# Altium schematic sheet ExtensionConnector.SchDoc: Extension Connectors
size A4; DocumentNumber: MB1167; Revision: B.1; SheetNumber: 14; SheetTotal: 17; Project: STM327x6G-EVAL
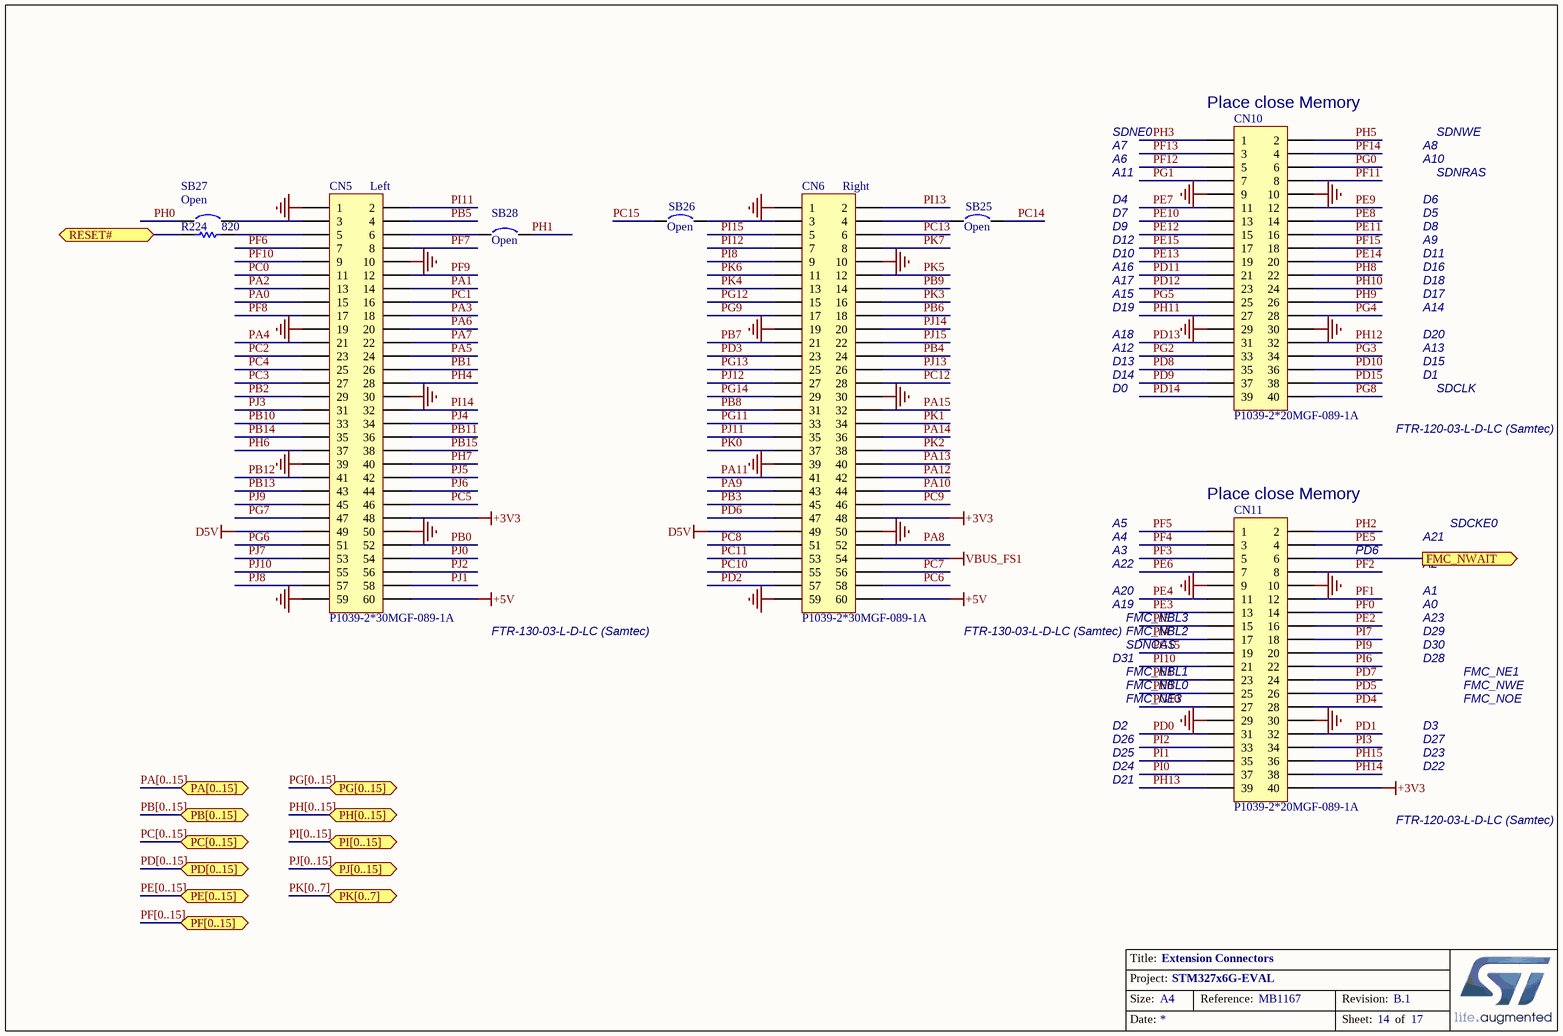
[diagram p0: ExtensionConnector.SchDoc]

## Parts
CN5  P1039-2*30MGF-089-1A  [FTR-130-53-L-D-LC]
CN6  P1039-2*30MGF-089-1A  [FTR-130-53-L-D-LC]
CN10  P1039-2*20MGF-089-1A  [FTR-120-53-L-D-LC]
CN11  P1039-2*20MGF-089-1A  [FTR-120-53-L-D-LC]
R224  820  [0603R]
SB25  Open  [SB_0603]
SB26  Open  [SB_0603]
SB27  Open  [SB_0603]
SB28  Open  [SB_0603]

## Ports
FMC_NWAIT (out), PA[0..15] (bidir), PB[0..15] (bidir), PC[0..15] (bidir), PD[0..15] (bidir), PE[0..15] (bidir), PF[0..15] (bidir), PG[0..15] (bidir), PH[0..15] (bidir), PI[0..15] (bidir), PJ[0..15] (bidir), PK[0..7] (bidir), RESET# (bidir)

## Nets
+3V3: CN5.48 CN6.48 CN11.40
+5V: CN5.60 CN6.60
D5V: CN5.49 CN6.49
GND: CN5.1 CN5.10 CN5.19 CN5.30 CN5.39 CN5.50 CN5.59 CN6.1 CN6.10 CN6.19 CN6.30 CN6.39 CN6.50 CN6.59 CN10.9 CN10.10 CN10.29 CN10.30 CN11.9 CN11.10 CN11.29 CN11.30
VBUS_FS1: CN6.54
FMC_NWAIT: CN11.6 ; port FMC_NWAIT
PA0: CN5.15
PA1: CN5.14
PA2: CN5.13
PA3: CN5.18
PA4: CN5.21
PA5: CN5.24
PA6: CN5.20
PA7: CN5.22
PA8: CN6.52
PA9: CN6.43
PA10: CN6.44
PA11: CN6.41
PA12: CN6.42
PA13: CN6.40
PA14: CN6.36
PA15: CN6.32
PB0: CN5.52
PB1: CN5.26
PB2: CN5.29
PB3: CN6.45
PB4: CN6.24
PB5: CN5.4
PB6: CN6.18
PB7: CN6.21
PB8: CN6.31
PB9: CN6.14
PB10: CN5.33
PB11: CN5.36
PB12: CN5.41
PB13: CN5.43
PB14: CN5.35
PB15: CN5.38
PC0: CN5.11
PC1: CN5.16
PC2: CN5.23
PC3: CN5.27
PC4: CN5.25
PC5: CN5.46
PC6: CN6.58
PC7: CN6.56
PC8: CN6.51
PC9: CN6.46
PC10: CN6.55
PC11: CN6.53
PC12: CN6.28
PC13: CN6.6
PC14: SB25.1
PC15: SB26.1
PD0: CN11.31
PD1: CN11.32
PD2: CN6.57
PD3: CN6.23
PD4: CN11.28
PD5: CN11.26
PD6: CN6.47
PD7: CN11.24
PD8: CN10.35
PD9: CN10.37
PD10: CN10.36
PD11: CN10.21
PD12: CN10.23
PD13: CN10.31
PD14: CN10.39
PD15: CN10.38
PE0: CN11.25
PE1: CN11.23
PE2: CN11.16
PE3: CN11.13
PE4: CN11.11
PE5: CN11.4
PE6: CN11.7
PE7: CN10.11
PE8: CN10.14
PE9: CN10.12
PE10: CN10.13
PE11: CN10.16
PE12: CN10.15
PE13: CN10.19
PE14: CN10.20
PE15: CN10.17
PF0: CN11.14
PF1: CN11.12
PF2: CN11.8
PF3: CN11.5
PF4: CN11.3
PF5: CN11.1
PF6: CN5.7
PF7: CN5.8
PF8: CN5.17
PF9: CN5.12
PF10: CN5.9
PF11: CN10.8
PF12: CN10.5
PF13: CN10.3
PF14: CN10.4
PF15: CN10.18
PG0: CN10.6
PG1: CN10.7
PG2: CN10.33
PG3: CN10.34
PG4: CN10.28
PG5: CN10.25
PG6: CN5.51
PG7: CN5.47
PG8: CN10.40
PG9: CN6.17
PG10: CN11.27
PG11: CN6.33
PG12: CN6.15
PG13: CN6.25
PG14: CN6.29
PG15: CN11.19
PH0: SB27.1
PH1: SB28.1
PH2: CN11.2
PH3: CN10.1
PH4: CN5.28
PH5: CN10.2
PH6: CN5.37
PH7: CN5.40
PH8: CN10.22
PH9: CN10.26
PH10: CN10.24
PH11: CN10.27
PH12: CN10.32
PH13: CN11.39
PH14: CN11.38
PH15: CN11.36
PI0: CN11.37
PI1: CN11.35
PI2: CN11.33
PI3: CN11.34
PI4: CN11.17
PI5: CN11.15
PI6: CN11.22
PI7: CN11.18
PI8: CN6.9
PI9: CN11.20
PI10: CN11.21
PI11: CN5.2
PI12: CN6.7
PI13: CN6.2
PI14: CN5.32
PI15: CN6.5
PJ0: CN5.54
PJ1: CN5.58
PJ2: CN5.56
PJ3: CN5.31
PJ4: CN5.34
PJ5: CN5.42
PJ6: CN5.44
PJ7: CN5.53
PJ8: CN5.57
PJ9: CN5.45
PJ10: CN5.55
PJ11: CN6.35
PJ12: CN6.27
PJ13: CN6.26
PJ14: CN6.20
PJ15: CN6.22
PK0: CN6.37
PK1: CN6.34
PK2: CN6.38
PK3: CN6.16
PK4: CN6.13
PK5: CN6.12
PK6: CN6.11
PK7: CN6.8
RESET#: R224.1 ; port RESET#
NetCN5_3: CN5.3 SB27.2
NetCN5_5: CN5.5 R224.2
NetCN5_6: CN5.6 SB28.2
NetCN6_3: CN6.3 SB26.2
NetCN6_4: CN6.4 SB25.2

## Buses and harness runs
bus PA[0..15] = port PA[0..15]
bus PB[0..15] = port PB[0..15]
bus PC[0..15] = port PC[0..15]
bus PD[0..15] = port PD[0..15]
bus PE[0..15] = port PE[0..15]
bus PF[0..15] = port PF[0..15]
bus PG[0..15] = port PG[0..15]
bus PH[0..15] = port PH[0..15]
bus PI[0..15] = port PI[0..15]
bus PJ[0..15] = port PJ[0..15]
bus PK[0..7] = port PK[0..7]

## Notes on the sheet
- (near CN10) Place close Memory
- A6
- A7
- A11
- SDNE0
- A8
- A10
- SDNRAS
- SDNWE
- (near CN5) Left
- (near CN6) Right
- D4
- D7
- D9
- D12
- D5
- D6
- D8
- A9
- A16
- A17
- D10
- A15
- D19
- D11
- A14
- D16
- D17
- D18
- D13
- D14
- A18
- A12
- D15
- D1
- A13
- D20
- D0
- (near CN10) FTR-120-03-L-D-LC (Samtec)
- SDCLK
- (near CN11) Place close Memory
- A22
- A3
- A4
- A5
- PD6
- A21
- A2
- SDCKE0
- (near CN5) FTR-130-03-L-D-LC (Samtec)
- (near CN6) FTR-130-03-L-D-LC (Samtec)
- A19
- A20
- SDNCAS
- FMC_NBL2
- FMC_NBL3
- A23
- A0
- A1
- D29
- D30
- D31
- FMC_NBL0
- FMC_NBL1
- FMC_NE3
- D28
- FMC_NOE
- FMC_NWE
- FMC_NE1
- D2
- D21
- D24
- D25
- D26
- D3
- D22
- D23
- D27
- (near CN11) FTR-120-03-L-D-LC (Samtec)

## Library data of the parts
CN5 CN6 = FTR-130-53-L-D-LC: Header, 40-Pin, Dual row
CN10 CN11 = FTR-120-53-L-D-LC: Header, 20-Pin, Dual row
R224 = res1: Resistor; Value: 1K
SB25-SB28 = Circuit Breaker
